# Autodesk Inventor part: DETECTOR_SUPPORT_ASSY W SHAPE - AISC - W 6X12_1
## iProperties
Shininess: 64.0
Length Units: 11272
Angle Units: 11279
Time Units: 11290
Mass Units: 11286
Length Display Precision: 3
Angle Display Precision: 2
Compacted: True
Part Number: DETECTOR_SUPPORT_ASSY W SHAPE - AISC - W 6X12_1
Document SubType Name: Modeling
Created: 2004-08
Designer: John Blackburn
Material: MILD_STEEL
Manufacturer: Standard
Standards Organization: Custom
Density: 0.0
Volumn: 0.0
Area: 0.0
PropertySet Name: Model Information
Control State: 0
Master: False
Checked Out: False
Author: John Blackburn
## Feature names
1. BaseExt [Extrusion]
2. Fillet1
